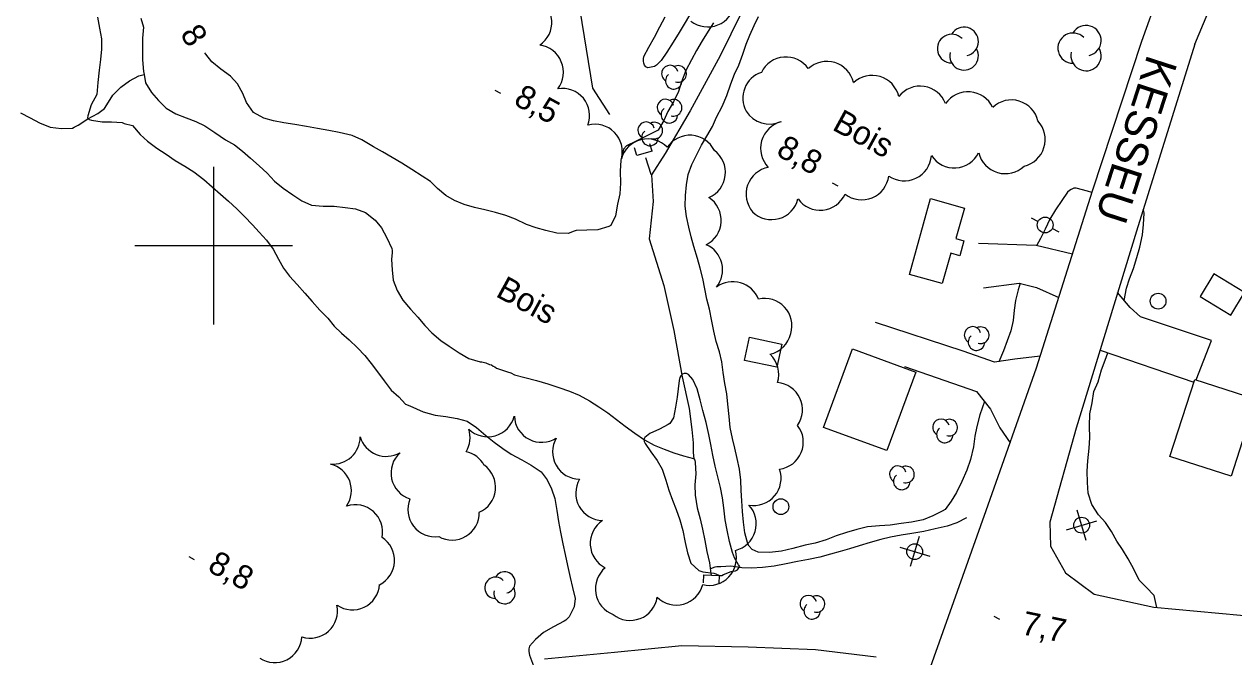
# Model space of a CAD drawing. Extents: x 219136 to 222520, y 5421589 to 5424530.
# Drawn here: x 220376 to 220529.4, y 5423147.8 to 5423228.1 of the extents above; entities that cross this region are included whole.
import ezdxf

# ---------------------------------------------------------------- set-up
doc = ezdxf.new("R2010")
doc.units = 0
for name, color, linetype in [('Level 1', 7, 'Continuous'), ('Level 19', 7, 'Continuous'), ('Level 2', 7, 'Continuous'), ('Level 21', 7, 'Continuous'), ('Level 22', 7, 'Continuous'), ('Level 26', 7, 'Continuous'), ('Level 3', 7, 'Continuous'), ('Level 31', 7, 'Continuous'), ('Level 36', 7, 'Continuous'), ('Level 4', 7, 'Continuous'), ('Level 44', 7, 'Continuous'), ('Level 61', 7, 'Continuous')]:
    doc.layers.add(name, color=color, linetype=linetype)

msp = doc.modelspace()

# ---------------------------------------------------------------- linework, layer by layer
at = {"layer": 'Level 1'}
for points in [[(220468, 5423242.63), (220467.34, 5423241.68), (220466.63, 5423240.35), (220466.01, 5423239.26), (220465.36, 5423238.19), (220464.62, 5423236.87), (220463.93, 5423235.6), (220463.24, 5423234.32), (220462.56, 5423233.06), (220461.9, 5423231.86), (220461.2, 5423230.69), (220460.54, 5423229.53), (220459.83, 5423228.31), (220459.05, 5423227.02), (220458.3, 5423225.81), (220457.48, 5423224.53), (220456.79, 5423223.49), (220456.2, 5423222.87), (220455.94, 5423222.73), (220455.1, 5423222.54), (220454.84, 5423222.68), (220454.67, 5423222.89)], [(220454.67, 5423222.89), (220454.57, 5423223.12), (220454.52, 5423223.39), (220454.53, 5423223.7), (220454.6, 5423223.96), (220455.21, 5423225.17), (220455.92, 5423226.42), (220456.6, 5423227.73), (220457.29, 5423229.02)]]:
    msp.add_lwpolyline(points, dxfattribs=at)
at = {"layer": 'Level 19'}
for points in [[(220508.95, 5423198.92), (220504.34, 5423199.99), (220497.05, 5423200.25)], [(220497.69, 5423194.64), (220502.19, 5423195.25), (220504.41, 5423194.67), (220507.22, 5423193.43)], [(220524.67, 5423182.96), (220526.59, 5423187.94), (220517.59, 5423190.96), (220516.28, 5423192.13), (220514.69, 5423194.03)], [(220504.87, 5423185.97), (220501.64, 5423185.57), (220499.07, 5423185.19), (220495.1, 5423186.62), (220483.99, 5423190.23)], [(220512.47, 5423186.73), (220524.36, 5423182.67)], [(220487.63, 5423184.64), (220496.79, 5423181.47), (220498.58, 5423179.23), (220499.75, 5423176.86), (220501.05, 5423174.96)]]:
    msp.add_lwpolyline(points, dxfattribs=at)
at = {"layer": 'Level 2'}
for points in [[(220385.28, 5423228.97), (220385.54, 5423227.56), (220385.8, 5423226.24), (220385.8, 5423224.92), (220385.65, 5423223.6), (220385.49, 5423222.23), (220385.33, 5423220.69), (220385.17, 5423219.18), (220384.48, 5423217.86), (220384.03, 5423216.47), (220384.02, 5423216.19), (220384.23, 5423216), (220384.51, 5423215.91), (220385.88, 5423215.69), (220387.07, 5423215.69), (220388.41, 5423215.59), (220388.64, 5423215.47), (220389.7, 5423215.22), (220389.7, 5423215.22)], [(220469.09, 5423161.11), (220468.34, 5423161.45), (220467.94, 5423161.87), (220467.79, 5423162.16), (220467.4, 5423163.58), (220467.22, 5423164.92), (220467.1, 5423166.26), (220467, 5423167.61), (220466.93, 5423168.94), (220466.88, 5423170.24), (220466.71, 5423171.63), (220466.43, 5423173.01), (220466.12, 5423174.28), (220465.82, 5423175.51), (220465.55, 5423176.94), (220465.39, 5423178.33), (220465.24, 5423179.87), (220465.1, 5423181.2), (220464.87, 5423182.5), (220464.64, 5423183.91), (220464.47, 5423185.25), (220464.17, 5423186.5), (220463.76, 5423187.85), (220463.47, 5423189.14), (220463.21, 5423190.41), (220462.92, 5423191.92), (220462.59, 5423193.22), (220462.33, 5423194.53), (220462.05, 5423195.82), (220461.73, 5423197.12), (220461.37, 5423198.35), (220460.94, 5423199.87), (220460.59, 5423201.1), (220460.31, 5423202.35), (220459.99, 5423203.7), (220459.83, 5423204.98), (220459.88, 5423206.37), (220459.99, 5423207.72), (220460.2, 5423209.01), (220460.69, 5423210.28), (220461.31, 5423211.55), (220461.9, 5423212.72), (220462.56, 5423213.88), (220463.28, 5423215.08), (220463.82, 5423216.29), (220464.5, 5423217.65), (220465.1, 5423219.05), (220465.62, 5423220.53), (220466.08, 5423221.74), (220466.62, 5423222.9), (220467.14, 5423224.29), (220467.57, 5423225.53), (220468.04, 5423226.7), (220468.58, 5423227.91), (220469.14, 5423229.06)], [(220463.42, 5423228.26), (220462.74, 5423227.2), (220461.97, 5423225.97), (220461.28, 5423224.76), (220460.64, 5423223.54), (220459.93, 5423222.22), (220459.34, 5423220.77), (220458.97, 5423219.53), (220458.34, 5423218.21), (220457.62, 5423217.01), (220457.11, 5423215.85), (220456.38, 5423214.65), (220456.13, 5423214.53), (220454.87, 5423213.86), (220453.63, 5423213.23), (220452.38, 5423212.63), (220452.02, 5423212.21), (220451.66, 5423210.81), (220451.58, 5423209.43), (220451.61, 5423207.91), (220451.53, 5423206.57), (220451.23, 5423205.25), (220450.98, 5423203.78), (220450.39, 5423202.56), (220450.14, 5423202.4), (220448.76, 5423202), (220447.36, 5423201.95), (220445.98, 5423201.92), (220445.73, 5423201.84), (220444.98, 5423201.52)], [(220444.98, 5423201.52), (220443.53, 5423201.59), (220442.16, 5423201.93), (220440.92, 5423202.24), (220439.69, 5423202.68), (220438.29, 5423203.35), (220437.07, 5423203.82), (220435.78, 5423204.19), (220434.4, 5423204.53), (220433.08, 5423204.84), (220431.8, 5423205.22), (220430.57, 5423205.71), (220429.48, 5423206.33), (220428.41, 5423207.23), (220427.5, 5423208.11), (220426.47, 5423208.82), (220425.14, 5423209.65), (220423.88, 5423210.44), (220422.66, 5423211.17), (220421.42, 5423211.89), (220420.3, 5423212.52), (220418.82, 5423213.4), (220417.56, 5423213.97), (220415.95, 5423214.34), (220414.62, 5423214.58), (220413.19, 5423214.85), (220411.77, 5423215.1), (220410.31, 5423215.35), (220408.91, 5423215.56), (220407.6, 5423215.8), (220406.39, 5423216.14), (220405.06, 5423216.87), (220404.17, 5423218.13), (220403.7, 5423219.29), (220403.03, 5423220.5), (220402.16, 5423221.48), (220400.91, 5423222.37), (220399.77, 5423223.29), (220399, 5423224.27), (220398.89, 5423224.45)], [(220389.7, 5423215.22), (220390.7, 5423214.09), (220391.63, 5423213.23), (220392.79, 5423212.35), (220393.99, 5423211.6), (220395.12, 5423210.8), (220396.35, 5423210.06), (220397.51, 5423209.36), (220398.76, 5423208.39), (220399.82, 5423207.46), (220400.86, 5423206.51), (220401.88, 5423205.65), (220402.95, 5423204.67), (220403.92, 5423203.69), (220404.92, 5423202.63), (220405.79, 5423201.71), (220406.7, 5423200.7), (220407.54, 5423199.53), (220408.24, 5423198.28), (220408.88, 5423197.12), (220409.63, 5423196.11), (220410.62, 5423195.06), (220411.59, 5423193.98), (220412.52, 5423192.9), (220413.49, 5423191.82), (220414.48, 5423190.78), (220415.28, 5423189.76), (220416.22, 5423188.87), (220417.2, 5423188.06), (220418.25, 5423187.03), (220419.2, 5423186.04), (220419.99, 5423185.03), (220420.8, 5423183.97), (220421.66, 5423182.85), (220422.52, 5423181.67), (220423.5, 5423180.8), (220424.36, 5423179.88)], [(220511.4, 5423206.72), (220510.86, 5423206.9), (220509.41, 5423207.26), (220509.12, 5423207.26), (220508.79, 5423207.12), (220508.57, 5423206.98), (220508.35, 5423206.77), (220507.59, 5423205.72), (220506.82, 5423204.55), (220506.1, 5423203.35), (220505.48, 5423202.09), (220504.91, 5423200.91), (220504.4, 5423199.98)], [(220517.97, 5423202.69), (220518.06, 5423204.11), (220518, 5423204.36), (220517.92, 5423204.52)], [(220515.52, 5423193.04), (220515.81, 5423194.61), (220516.2, 5423195.8), (220516.7, 5423197.11), (220517.11, 5423198.49), (220517.5, 5423199.8), (220517.83, 5423201.35), (220517.97, 5423202.69)], [(220502.33, 5423195.21), (220502.06, 5423194.37), (220501.72, 5423193.04), (220501.58, 5423191.8), (220501.44, 5423190.48), (220501.12, 5423189.19), (220500.67, 5423187.92), (220500.21, 5423186.66), (220499.62, 5423185.27)], [(220519.68, 5423154.11), (220519.33, 5423155.63), (220518.3, 5423156.65), (220517.43, 5423157.57), (220516.76, 5423158.96), (220516.04, 5423160.28), (220515.32, 5423161.46), (220514.58, 5423162.52), (220513.92, 5423163.72), (220513.15, 5423164.89), (220512.27, 5423165.86), (220511.4, 5423167.16), (220510.97, 5423168.61), (220510.87, 5423169.94), (220510.81, 5423171.37), (220510.9, 5423172.7), (220511.07, 5423174.29), (220511.15, 5423175.62), (220511.11, 5423177.1), (220511.16, 5423178.64), (220511.46, 5423180.06), (220511.65, 5423181.47), (220512.23, 5423182.73), (220512.66, 5423184.22), (220513.1, 5423185.46), (220513.44, 5423186.4)], [(220465.81, 5423161.07), (220465.46, 5423162.47), (220465.14, 5423163.92), (220464.92, 5423165.19), (220464.71, 5423166.75), (220464.55, 5423168.02), (220464.29, 5423169.32), (220463.96, 5423170.67), (220463.63, 5423172), (220463.32, 5423173.41), (220463.07, 5423174.77), (220462.82, 5423176.03), (220462.47, 5423177.56), (220462.08, 5423179.07), (220461.73, 5423180.42), (220461.34, 5423181.82), (220460.81, 5423183), (220460.25, 5423183.65), (220460, 5423183.76), (220459.72, 5423183.78), (220459.49, 5423183.69), (220459.28, 5423183.48), (220459.17, 5423183.25), (220459.06, 5423182.87), (220458.81, 5423180.76), (220458.61, 5423179.49), (220458.34, 5423178.14), (220457.9, 5423177.42), (220457.68, 5423177.3), (220456.56, 5423176.73), (220455.36, 5423176.18), (220454.72, 5423175.67), (220454.6, 5423175.41), (220454.62, 5423175.13), (220454.74, 5423174.91), (220455.47, 5423173.83), (220456.28, 5423172.74), (220456.9, 5423171.65), (220457.37, 5423170.25), (220457.77, 5423168.97), (220458.2, 5423167.71), (220458.69, 5423166.52), (220459.16, 5423165.23), (220459.52, 5423163.84), (220459.82, 5423162.33), (220460.12, 5423161.03), (220460.55, 5423159.73), (220461.54, 5423158.8), (220462.07, 5423158.61), (220463.46, 5423158.46), (220463.7, 5423158.35), (220464.2, 5423158.13), (220464.46, 5423158.15), (220464.7, 5423158.28), (220465.67, 5423158.65), (220466.21, 5423158.75), (220466.46, 5423158.88), (220466.75, 5423159.28), (220466.61, 5423159.52), (220466.09, 5423160.39), (220465.81, 5423161.07)], [(220424.36, 5423179.88), (220424.9, 5423179.66), (220426.57, 5423178.89), (220428.09, 5423178.49), (220429.46, 5423178.3), (220430.9, 5423178.08), (220432.15, 5423177.74), (220433.34, 5423176.93), (220434.55, 5423175.92), (220435.58, 5423175.07), (220436.69, 5423174.24), (220437.75, 5423173.53), (220439.09, 5423172.81), (220440.29, 5423172.16), (220441.57, 5423171.29), (220442.32, 5423170.29), (220442.88, 5423169.15), (220443.31, 5423167.93), (220443.54, 5423166.4), (220443.75, 5423165.02), (220444.01, 5423163.65), (220444.31, 5423162.17), (220444.61, 5423160.8), (220444.91, 5423159.4), (220445.23, 5423157.9), (220445.52, 5423156.64), (220445.86, 5423155.22), (220445.75, 5423154.19), (220445.11, 5423152.91), (220444.7, 5423152.48), (220444.46, 5423152.36), (220443.12, 5423151.64), (220441.85, 5423150.94), (220440.83, 5423150.04), (220440.09, 5423149.19), (220440, 5423148.84), (220439.98, 5423148.53), (220440.08, 5423148.03), (220440.59, 5423146.71)], [(220497.78, 5423180.23), (220497.22, 5423178.51), (220496.84, 5423177.05), (220496.58, 5423175.83), (220496.4, 5423174.45), (220496.04, 5423172.88), (220495.54, 5423171.52), (220494.92, 5423170.07), (220494.24, 5423168.68), (220493.56, 5423167.59), (220492.79, 5423166.54), (220492.45, 5423166.31), (220491.26, 5423165.7), (220490.01, 5423165.22), (220488.55, 5423164.93), (220487.23, 5423164.73), (220485.83, 5423164.55), (220484.49, 5423164.45), (220482.95, 5423164.31), (220481.59, 5423164), (220480.28, 5423163.61), (220478.99, 5423163.16), (220477.73, 5423162.69), (220476.33, 5423162.27), (220475.03, 5423162), (220473.49, 5423161.59), (220472.04, 5423161.23), (220470.51, 5423161.07), (220469.09, 5423161.11)]]:
    msp.add_lwpolyline(points, dxfattribs=at)
at = {"layer": 'Level 21'}
for points in [[(220524.5, 5423225.55), (220528, 5423233.97), (220531.06, 5423236.5), (220537.29, 5423238.65), (220543.86, 5423238.88), (220587.76, 5423236.74), (220590.58, 5423236.58), (220612.48, 5423235.35), (220616.98, 5423235.23), (220629.62, 5423234.88), (220641.35, 5423233.79), (220643.81, 5423233.56), (220649.45, 5423233.75), (220658.93, 5423234.08), (220677.49, 5423234.68)], [(220490.29, 5423144.63), (220498.03, 5423166.39), (220504.4, 5423184.49), (220511.48, 5423206.96), (220517.78, 5423225.93), (220519.9, 5423231.95)], [(220524.5, 5423225.55), (220517.07, 5423201.81), (220509.44, 5423176.82), (220506.09, 5423164.9), (220506.17, 5423161.85), (220508.06, 5423158.48), (220511.7, 5423155.79), (220519.29, 5423154.15), (220533.01, 5423152.88), (220544.86, 5423152.11), (220554.83, 5423151.86), (220559.39, 5423152.13)]]:
    msp.add_lwpolyline(points, dxfattribs=at)
at = {"layer": 'Level 22'}
for points in [[(220450.26, 5423216.62), (220448.11, 5423219.97), (220446.5, 5423229.86), (220440.13, 5423235.13), (220434.85, 5423241.07), (220431.08, 5423249.4), (220427.46, 5423254.64), (220426.22, 5423263.43), (220423.31, 5423272.49), (220420.82, 5423285.27), (220418.58, 5423299.6), (220416.25, 5423313.29), (220414.57, 5423324.25), (220413.95, 5423330.18), (220414.16, 5423333.43), (220414.16, 5423333.43)], [(220484.07, 5423147.78), (220476.34, 5423148.72), (220467.82, 5423149.04), (220459.42, 5423149.24), (220450.88, 5423148.4), (220441.97, 5423147.55)]]:
    msp.add_lwpolyline(points, dxfattribs=at)
at = {"layer": 'Level 26'}
for p, q in [((220453.68, 5423211.42), (220453.41, 5423212.38)), ((220455.62, 5423211.96), (220455.35, 5423212.92)), ((220455.62, 5423211.96), (220453.68, 5423211.42)), ((220462.14, 5423158.23), (220462.09, 5423157.23)), ((220462.14, 5423158.23), (220464.16, 5423158.13)), ((220464.16, 5423158.13), (220464.11, 5423157.13))]:
    msp.add_line(p, q, dxfattribs=at)
at = {"layer": 'Level 3'}
for p, q in [((220435.69, 5423219.73), (220436.39, 5423219.34)), ((220478.49, 5423207.95), (220479.19, 5423207.56)), ((220396.85, 5423160.55), (220397.55, 5423160.17)), ((220499, 5423153.01), (220499.7, 5423152.63))]:
    msp.add_line(p, q, dxfattribs=at)
at = {"layer": 'Level 31'}
for points in [[(220488.28, 5423196.34), (220490.96, 5423205.95), (220495.26, 5423204.75), (220494.18, 5423200.89), (220495.19, 5423200.6), (220494.66, 5423198.71), (220493.51, 5423199.03), (220492.43, 5423195.18)], [(220526.91, 5423196.43), (220525.15, 5423193.54), (220529.03, 5423191.18), (220530.79, 5423194.06)], [(220467.97, 5423188.37), (220472.09, 5423187.51), (220471.47, 5423184.56), (220467.35, 5423185.43)], [(220489.08, 5423183.95), (220485.41, 5423173.99), (220477.38, 5423176.94), (220481.05, 5423186.9)], [(220532.24, 5423180.51), (220529.09, 5423170.74), (220521.32, 5423173.24), (220524.47, 5423183.02)]]:
    msp.add_lwpolyline(points, close=True, dxfattribs=at)
at = {"layer": 'Level 36'}
for p, q in [((220503.73, 5423203.52), (220504.62, 5423203.07)), ((220507.28, 5423201.68), (220506.39, 5423202.15)), ((220510.69, 5423162.61), (220509.56, 5423166.44)), ((220508.21, 5423163.96), (220512.04, 5423165.09)), ((220489.53, 5423163.08), (220488.36, 5423159.27)), ((220487.04, 5423161.76), (220490.85, 5423160.59))]:
    msp.add_line(p, q, dxfattribs=at)
for centre in [(220505.5, 5423202.61), (220519.82, 5423192.95), (220471.97, 5423166.88), (220510.13, 5423164.53), (220488.94, 5423161.17)]:
    msp.add_circle(centre, 1, dxfattribs=at)
at = {"layer": 'Level 4'}
for points in [[(220504.73, 5423342.78), (220502.36, 5423334.07), (220498.83, 5423324.77), (220497.68, 5423314.99), (220494.88, 5423302.37), (220492.18, 5423292.16), (220488.58, 5423279.78), (220486.21, 5423268.82), (220481.43, 5423255.76), (220478.87, 5423250.06), (220474.26, 5423242.43), (220468.32, 5423232.37), (220464.27, 5423224.08), (220460.45, 5423217.08), (220457.28, 5423211.66), (220455.56, 5423208.98)], [(220390.79, 5423228.85), (220391.09, 5423227.72), (220391, 5423226.29), (220390.97, 5423225.03), (220390.97, 5423223.56), (220391.11, 5423222.07), (220391.18, 5423221.7)], [(220375.51, 5423216.82), (220376.74, 5423216.2), (220377.92, 5423215.58), (220379.25, 5423215.03), (220380.69, 5423214.83), (220382.09, 5423214.9), (220382.33, 5423215), (220382.81, 5423215.29), (220384.05, 5423216.07), (220385.32, 5423216.75), (220386.15, 5423217.4), (220386.47, 5423217.87), (220387.2, 5423219.06), (220388.24, 5423220.09), (220389.35, 5423220.88), (220390.53, 5423221.51), (220391.18, 5423221.7), (220391.18, 5423221.7)], [(220391.18, 5423221.7), (220391.36, 5423220.66), (220392.14, 5423219.41), (220393.02, 5423218.38), (220394, 5423217.43)], [(220394, 5423217.43), (220395.2, 5423216.71), (220396.52, 5423216.19), (220397.74, 5423215.75), (220398.89, 5423215.2), (220400.16, 5423214.35), (220401.51, 5423213.41), (220402.65, 5423212.78), (220403.67, 5423211.97), (220404.7, 5423211.1), (220405.78, 5423210.13), (220406.8, 5423209.17), (220407.71, 5423208.17), (220408.84, 5423207.26), (220410.04, 5423206.45), (220411.2, 5423205.68), (220412.41, 5423205.14), (220413.91, 5423205.01), (220415.28, 5423204.99), (220416.71, 5423204.84), (220418.01, 5423204.64), (220419.26, 5423204.18), (220420.49, 5423203.22), (220421.29, 5423202.25), (220421.97, 5423200.98), (220422.61, 5423199.63), (220422.66, 5423199.36), (220422.64, 5423199.11), (220422.58, 5423198.25), (220422.67, 5423196.92), (220422.79, 5423195.63), (220423.31, 5423194.29), (220424, 5423193.09), (220424.99, 5423191.93), (220425.91, 5423190.92), (220426.79, 5423189.84), (220427.67, 5423188.91), (220428.82, 5423187.94), (220429.87, 5423187.23), (220431.14, 5423186.41), (220432.4, 5423185.67), (220433.8, 5423185.25), (220434.05, 5423185.27)], [(220454.79, 5423211.18), (220455.47, 5423209.07), (220455.56, 5423208.98)], [(220455.56, 5423208.98), (220455.77, 5423205.57), (220455.27, 5423200.85), (220457.1, 5423194.94), (220458.37, 5423189.24), (220459.44, 5423183.35), (220460.32, 5423179.35), (220460.68, 5423176.66), (220460.86, 5423174.98), (220460.82, 5423173.76), (220460.91, 5423172.95)], [(220434.05, 5423185.27), (220434.55, 5423185.14), (220435, 5423184.93), (220435.25, 5423184.87), (220435.45, 5423184.72), (220435.69, 5423184.61), (220435.88, 5423184.44), (220437.3, 5423183.97)], [(220437.3, 5423183.97), (220437.73, 5423183.86), (220438.19, 5423183.62), (220439.48, 5423183.27), (220440.95, 5423182.88), (220442.41, 5423182.48), (220443.82, 5423182), (220445.16, 5423181.55), (220446.39, 5423181.04), (220447.71, 5423180.32), (220448.89, 5423179.54), (220450.02, 5423178.78), (220451.13, 5423177.95), (220452.22, 5423177.08), (220453.42, 5423176.21), (220454.67, 5423175.36), (220455.88, 5423174.7), (220457.18, 5423174.18), (220458.38, 5423173.69), (220459.62, 5423173.32), (220460.88, 5423172.98), (220460.91, 5423172.95)], [(220460.91, 5423172.95), (220461.04, 5423172.77), (220461.1, 5423172.5), (220461.16, 5423171.06), (220461.07, 5423169.64), (220461.1, 5423168.34), (220461.33, 5423166.74), (220461.73, 5423165.35), (220462.03, 5423164.02), (220462.33, 5423162.61), (220462.57, 5423161.18), (220462.93, 5423159.74), (220463.09, 5423158.41), (220463.14, 5423158.18)], [(220495.53, 5423165.47), (220494.31, 5423164.82), (220493.08, 5423164.4), (220491.55, 5423164.05), (220490.09, 5423163.73), (220488.58, 5423163.46), (220487.21, 5423163.25), (220485.88, 5423163.02), (220484.64, 5423162.7), (220483.29, 5423162.32), (220481.91, 5423161.92), (220480.69, 5423161.55), (220479.48, 5423161.21), (220478.25, 5423160.85), (220476.91, 5423160.49), (220475.46, 5423160.16), (220474.08, 5423159.91), (220472.63, 5423159.62), (220471.12, 5423159.34), (220469.63, 5423159.18), (220468.25, 5423159.09), (220467, 5423159.14), (220465.62, 5423159.32), (220464.33, 5423159.26), (220463.83, 5423159.23), (220463.57, 5423159.19), (220463.06, 5423159.01), (220463.02, 5423159)]]:
    msp.add_lwpolyline(points, dxfattribs=at)
at = {"layer": 'Level 44'}
for centre, radius, start, end in [((220439.45, 5423228.31), 3.46, 303.7796, 63.7796), ((220462.69, 5423231.2), 3.46, 231.8105, 351.8105), ((220495.2, 5423225.89), 1.82, 282.2692, 149.7262), ((220510.68, 5423226), 1.92, 282.2692, 149.7262), ((220493.64, 5423224.98), 1.82, 44.1153, 269.8039), ((220509.03, 5423225.04), 1.92, 44.1153, 269.8039), ((220440.92, 5423221.99), 3.46, 322.5691, 82.5691), ((220495.2, 5423224.07), 1.82, 166.9368, 29.6212), ((220510.68, 5423224.08), 1.92, 166.9368, 29.6212), ((220457.89, 5423221.81), 1.05, 14.9746, 237.6589), ((220458.93, 5423221.77), 1.05, 252.1531, 117.8417), ((220472.61, 5423220.46), 3.46, 34.8896, 154.2318), ((220477.8, 5423219.9), 3.46, 12.7251, 132.7251), ((220458.38, 5423220.89), 1.05, 130.3069, 357.764), ((220470.6, 5423218.69), 3.46, 108.7063, 208.4036), ((220483.55, 5423218.13), 3.46, 13.2003, 133.2003), ((220444.25, 5423216.47), 3.46, 339.6064, 99.6064), ((220489.63, 5423216.76), 3.46, 21.2985, 141.2985), ((220457.33, 5423217.51), 1.05, 14.9746, 237.6589), ((220458.37, 5423217.47), 1.05, 252.1531, 117.8417), ((220495.71, 5423216.05), 3.46, 25.4232, 145.4232), ((220501.21, 5423215.01), 3.46, 13.2475, 133.2475), ((220457.82, 5423216.59), 1.05, 130.3069, 357.764), ((220470.5, 5423218.87), 3.46, 211.8742, 295.1429), ((220448.39, 5423211.92), 3.46, 344.8264, 104.8264), ((220454.88, 5423214.63), 1.05, 14.9746, 237.6589), ((220455.92, 5423214.59), 1.05, 252.1531, 117.8417), ((220472.85, 5423212.34), 3.46, 104.3541, 224.3541), ((220502.04, 5423213.45), 3.46, 282.9151, 42.9151), ((220455.06, 5423210.06), 3.46, 44.0479, 164.0479), ((220455.37, 5423213.71), 1.05, 130.3069, 357.764), ((220460.42, 5423210.53), 3.46, 26.0113, 146.0113), ((220461.47, 5423209.27), 3.46, 293.4011, 53.4011), ((220487.62, 5423211.67), 3.46, 235.4639, 355.4639), ((220493.96, 5423213.31), 3.46, 213.4607, 333.4607), ((220500.43, 5423212.58), 3.46, 193.6509, 313.6509), ((220471.01, 5423206.51), 3.46, 100.5755, 220.5755), ((220482.22, 5423209.27), 3.46, 232.5174, 352.5174), ((220460.94, 5423203.19), 3.46, 296.7166, 56.7166), ((220470.78, 5423206.75), 3.46, 225.9694, 345.9694), ((220476.95, 5423207.94), 3.46, 215.8754, 335.8754), ((220461.12, 5423196.92), 3.46, 321.0277, 66.5726), ((220465.88, 5423191.96), 3.46, 21.0277, 126.5726), ((220469.91, 5423189.83), 3.46, 343.1865, 103.1865), ((220496.29, 5423188.67), 1.05, 14.9746, 237.6589), ((220497.33, 5423188.63), 1.05, 252.1531, 117.8417), ((220469.84, 5423189.59), 3.46, 282.4222, 347.242), ((220496.78, 5423187.75), 1.05, 130.3069, 357.764), ((220468.24, 5423183.67), 3.46, 342.4222, 47.242), ((220471.25, 5423179.17), 3.46, 325.1727, 85.1727), ((220434.79, 5423179.2), 3.46, 225.7233, 345.7233), ((220441.61, 5423178.5), 3.46, 182.6498, 302.6498), ((220429.08, 5423175.65), 3.46, 328.6933, 17.9705), ((220471.35, 5423175.07), 3.46, 277.6672, 37.6672), ((220492.29, 5423176.95), 1.05, 14.9746, 237.6589), ((220492.78, 5423176.03), 1.05, 130.3069, 357.764), ((220493.33, 5423176.91), 1.05, 252.1531, 117.8417), ((220415.14, 5423175.74), 3.46, 265.1657, 359.929), ((220421.92, 5423176.72), 3.46, 196.489, 299.929), ((220446.46, 5423173.83), 3.46, 149.5023, 269.5023), ((220425.97, 5423171.15), 3.46, 132.0764, 252.0764), ((220431.31, 5423170.46), 3.46, 28.6933, 77.9705), ((220414.03, 5423168.92), 3.46, 325.1657, 76.489), ((220432.31, 5423169.33), 3.46, 293.8767, 53.8767), ((220468.54, 5423170.49), 3.46, 259.3474, 19.3474), ((220486.81, 5423171), 1.05, 14.9746, 237.6589), ((220487.3, 5423170.08), 1.05, 130.3069, 357.764), ((220487.85, 5423170.96), 1.05, 252.1531, 117.8417), ((220449.4, 5423168.58), 3.46, 148.9548, 268.9548), ((220428.11, 5423166.52), 3.46, 157.4762, 277.4762), ((220417.99, 5423163.66), 3.46, 348.6482, 108.6482), ((220430.25, 5423166.11), 3.46, 240.7602, 0.7602), ((220465.39, 5423164.7), 3.46, 283.5016, 43.5016), ((220451.24, 5423162.22), 3.46, 123.3456, 243.3456), ((220419.49, 5423160.07), 3.46, 296.9747, 56.9747), ((220462.87, 5423160.36), 3.46, 256.3167, 16.3167), ((220436.91, 5423157.26), 1.35, 282.2692, 149.7262), ((220451.89, 5423156.46), 3.46, 129.5868, 249.5868), ((220417.61, 5423157.25), 3.46, 235.6955, 355.6955), ((220435.75, 5423156.59), 1.35, 44.1153, 269.8039), ((220458.7, 5423157.86), 3.46, 225.5193, 345.5193), ((220436.91, 5423155.91), 1.35, 166.9368, 29.6212), ((220452.85, 5423155.91), 3.46, 231.3267, 351.3267), ((220475.46, 5423154.58), 1.05, 14.9746, 237.6589), ((220476.5, 5423154.54), 1.05, 252.1531, 117.8417), ((220412.27, 5423153.66), 3.46, 252.0356, 12.0356), ((220475.95, 5423153.66), 1.05, 130.3069, 357.764), ((220407.74, 5423150.56), 3.46, 236.8312, 356.8312)]:
    msp.add_arc(centre, radius, start, end, dxfattribs=at)
at = {"layer": 'Level 61'}
for points in [[(220400, 5423210), (220400, 5423200), (220400, 5423190)], [(220390, 5423200), (220400, 5423200), (220410, 5423200)]]:
    msp.add_lwpolyline(points, dxfattribs=at)

# ---------------------------------------------------------------- texts
at = {"layer": 'Level 2'}
msp.add_text('8', height=3, rotation=301.8333, dxfattribs=at).set_placement((220395.68, 5423226.85))
at = {"layer": 'Level 21'}
msp.add_text('KESSEU', height=4, rotation=252.1442, dxfattribs=at).set_placement((220518.5, 5423224.36))
at = {"layer": 'Level 3'}
for s, rotation, p in [('8,5', 331.383, (220437.92, 5423217.98)), ('8,8', 331.383, (220471.23, 5423211.53)), ('8,8', 331.383, (220399.09, 5423158.81)), ('7,7', 348.2738, (220502.34, 5423150.73))]:
    msp.add_text(s, height=3, rotation=rotation, dxfattribs=at).set_placement(p)
at = {"layer": 'Level 44'}
for p in [(220478.34, 5423214.76), (220435.66, 5423193.62)]:
    msp.add_text('Bois', height=3, rotation=331.3547, dxfattribs=at).set_placement(p)

doc.saveas('drawing.dxf')
